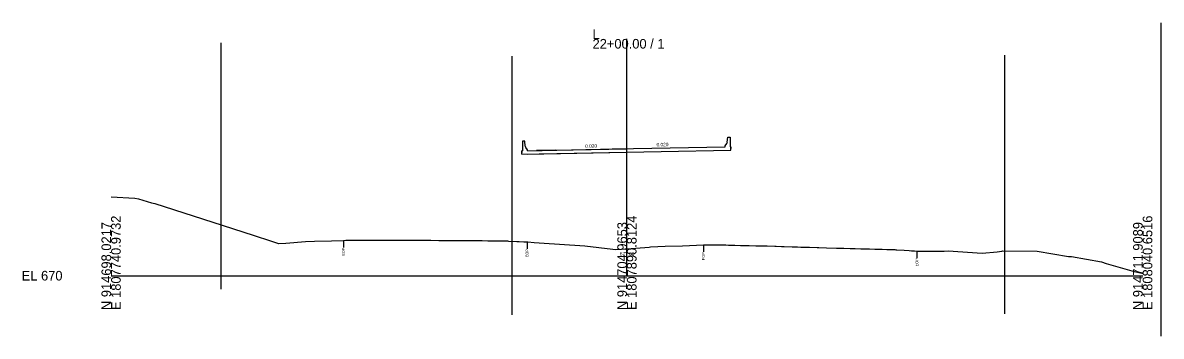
# Model space of a CAD drawing. Extents: x -26 to 1352, y -510 to 9596.
# Drawn here: x -25.7 to 305.4, y 7982.4 to 8073.6 of the extents above; entities that cross this region are included whole.
import ezdxf

# ---------------------------------------------------------------- set-up
doc = ezdxf.new("R2010")
doc.units = 0
for name, color, linetype in [('Default', 7, 'Continuous'), ('Exist Cross Section Cell', 7, 'Continuous'), ('Exist XS Center Line Elevation Label', 7, 'Continuous'), ('Exist XS Ground Line', 7, 'Continuous'), ('Old_Level_10', 7, 'Continuous'), ('Prop XS Bridge', 7, 'Continuous'), ('Prop XS Exc Vertical Line 1', 7, 'Continuous'), ('Prop XS Exc Vertical Line 2', 7, 'Continuous'), ('Prop XS Exc Vertical Line 3', 7, 'Continuous'), ('Prop XS Exc Vertical Line 4', 7, 'Continuous'), ('Prop XS SE Text', 7, 'Continuous')]:
    doc.layers.add(name, color=color, linetype=linetype)

msp = doc.modelspace()

# ---------------------------------------------------------------- linework, layer by layer
at = {"layer": 'Default'}
for p, q in [((119.63, 8039.14), (119.59, 8039.1)), ((119.59, 8039.1), (119.59, 8036.36)), ((120.26, 8039.14), (119.63, 8039.14)), ((120.29, 8039.1), (120.26, 8039.14)), ((120.44, 8037.71), (120.29, 8039.1)), ((179.2, 8038.86), (179.35, 8040.25)), ((179.35, 8040.25), (179.39, 8040.29)), ((179.39, 8040.29), (180.02, 8040.29)), ((180.02, 8040.29), (180.05, 8040.25)), ((180.05, 8040.25), (180.05, 8037.51)), ((119.46, 8035.32), (180.18, 8036.54)), ((119.53, 8036.36), (119.46, 8036.29)), ((119.46, 8035.32), (119.46, 8036.29)), ((119.46, 8036.29), (119.46, 8035.83)), ((119.59, 8036.36), (119.53, 8036.36)), ((121.07, 8036.62), (120.59, 8037.3)), ((121.07, 8036.36), (146.57, 8036.87)), ((121.07, 8036.36), (121.07, 8036.62)), ((121.09, 8035.36), (149.82, 8035.93)), ((150, 8036.93), (145.71, 8036.85)), ((146.57, 8036.87), (178.57, 8037.51)), ((178.57, 8037.77), (179.05, 8038.45)), ((178.57, 8037.51), (178.57, 8037.77)), ((180.05, 8037.51), (180.11, 8037.51)), ((180.11, 8037.51), (180.18, 8037.44)), ((180.18, 8037.44), (180.18, 8036.98)), ((180.18, 8036.54), (180.18, 8037.44))]:
    msp.add_line(p, q, dxfattribs=at)
for centre, start, end in [((178.34, 8038.95), 325.0087, 353.9889), ((121.3, 8037.8), 186.0111, 214.9913)]:
    msp.add_arc(centre, 0.869, start, end, dxfattribs=at)
at = {"layer": 'Exist Cross Section Cell'}
for p, q in [((150, 8000), (150, 8068.87)), ((0, 8000), (150, 8000)), ((150, 8000), (300, 8000))]:
    msp.add_line(p, q, dxfattribs=at)
at = {"layer": 'Exist XS Ground Line'}
msp.add_lwpolyline([(0, 8022.96), (6.93, 8022.55), (7.94, 8022.38), (11.73, 8021.21), (12.72, 8020.99), (32.33, 8014.67), (41.63, 8011.7), (46.33, 8010.11), (48.67, 8009.41), (48.81, 8009.37), (50.85, 8009.43), (56.48, 8009.92), (59.17, 8010.01), (64.11, 8010.17), (67.55, 8010.28), (68.27, 8010.29), (69.29, 8010.29), (70.41, 8010.31), (71.39, 8010.31), (72.94, 8010.32), (74.61, 8010.32), (75.42, 8010.32), (77.27, 8010.33), (77.91, 8010.33), (79.87, 8010.33), (80.7, 8010.35), (82.19, 8010.38), (82.68, 8010.37), (82.94, 8010.37), (85.11, 8010.35), (85.42, 8010.35), (85.69, 8010.35), (87.92, 8010.33), (90.39, 8010.32), (90.45, 8010.32), (91.65, 8010.31), (92.88, 8010.3), (92.93, 8010.3), (95.26, 8010.28), (95.44, 8010.28), (95.63, 8010.28), (97.94, 8010.27), (98.28, 8010.27), (98.52, 8010.27), (100.16, 8010.26), (100.53, 8010.26), (100.85, 8010.25), (102.97, 8010.24), (103.5, 8010.24), (105.46, 8010.22), (107.19, 8010.2), (107.94, 8010.2), (109.6, 8010.17), (110.45, 8010.16), (112.05, 8010.15), (112.97, 8010.13), (114.96, 8010.12), (115.13, 8010.12), (115.31, 8010.1), (115.59, 8010.09), (117.97, 8009.94), (118.64, 8009.92), (120.04, 8009.87), (120.95, 8009.85), (121.2, 8009.84), (123.03, 8009.68), (124.48, 8009.59), (137.73, 8008.69), (145.93, 8007.69), (146.6, 8007.61), (150, 8007.86), (156.46, 8008.34), (156.89, 8008.37), (161.13, 8008.54), (166.18, 8008.73), (172.26, 8008.96), (172.89, 8008.96), (173.62, 8008.95), (175.53, 8008.93), (176.54, 8008.95), (177.71, 8008.93), (178.31, 8008.95), (178.72, 8008.94), (179.56, 8008.92), (180.53, 8008.89), (181.36, 8008.87), (183.04, 8008.83), (184.83, 8008.79), (185.54, 8008.77), (187.48, 8008.73), (188.05, 8008.72), (190.12, 8008.66), (190.55, 8008.64), (190.82, 8008.64), (192.97, 8008.57), (193.37, 8008.56), (194.92, 8008.5), (195.27, 8008.5), (195.54, 8008.49), (195.72, 8008.48), (198.07, 8008.41), (198.16, 8008.41), (199.65, 8008.37), (200.58, 8008.34), (200.64, 8008.34), (203.09, 8008.27), (205.32, 8008.2), (205.55, 8008.2), (205.8, 8008.19), (208.05, 8008.11), (210.94, 8008.02), (210.95, 8008.02), (210.95, 8008.02), (212.95, 8007.98), (213.07, 8007.98), (214.89, 8007.93), (215.56, 8007.92), (216.33, 8007.9), (218.06, 8007.85), (219.64, 8007.8), (220.57, 8007.78), (222.08, 8007.74), (223.09, 8007.72), (224.24, 8007.68), (225.6, 8007.65), (226.01, 8007.64), (227.93, 8007.58), (228.17, 8007.56), (228.53, 8007.54), (230.6, 8007.38), (232.09, 8007.29), (232.8, 8007.25), (233.62, 8007.21), (234.32, 8007.17), (236.64, 8007.18), (239.04, 8007.18), (240.86, 8007.18), (242.28, 8007.17), (243.43, 8007.19), (253.3, 8006.54), (257.69, 8006.98), (259.01, 8007.09), (259.02, 8007.12), (259.33, 8007.24), (269.32, 8007.14), (278.42, 8005.6), (279.33, 8005.59), (287.98, 8004.01), (289.34, 8003.57), (297.55, 8001.2), (299.35, 8000.82), (300, 8000.64)], dxfattribs=at)
at = {"layer": 'Old_Level_10'}
for p, q in [((67.55, 8010.28), (67.55, 8008.23)), ((120.95, 8009.85), (120.95, 8007.8)), ((172.26, 8008.96), (172.26, 8006.91)), ((234.32, 8007.17), (234.32, 8005.12))]:
    msp.add_line(p, q, dxfattribs=at)
at = {"layer": 'Prop XS Bridge'}
for q in [(123.75, 8036.41), (150, 8036.93)]:
    msp.add_line((129.25, 8036.52), q, dxfattribs=at)
at = {"layer": 'Prop XS Exc Vertical Line 1'}
msp.add_line((31.98, 7996.06), (31.98, 8067.72), dxfattribs=at)
at = {"layer": 'Prop XS Exc Vertical Line 2'}
msp.add_line((116.64, 7988.63), (116.64, 8063.87), dxfattribs=at)
at = {"layer": 'Prop XS Exc Vertical Line 3'}
msp.add_line((259.9, 7988.9), (259.9, 8064.14), dxfattribs=at)
at = {"layer": 'Prop XS Exc Vertical Line 4'}
msp.add_line((305.38, 7982.38), (305.38, 8073.58), dxfattribs=at)

# ---------------------------------------------------------------- texts
at = {"layer": 'Exist Cross Section Cell'}
for s, p in [('L', (140, 8068.87)), ('22+00.00 / 1', (140, 8066.07)), ('EL 670', (-26, 7998.6))]:
    msp.add_text(s, height=2.8, dxfattribs=at).set_placement(p)
for s, p in [('N 914698.0217', (0, 7990)), ('E 1807740.9732', (2.8, 7990)), ('N 914704.9653', (150, 7990)), ('E 1807890.8124', (152.8, 7990)), ('N 914711.9089', (300, 7990)), ('E 1808040.6516', (302.8, 7990))]:
    msp.add_text(s, height=2.8, rotation=90, dxfattribs=at).set_placement(p)
at = {"layer": 'Exist XS Center Line Elevation Label'}
msp.add_text('677.86', height=1, dxfattribs=at).set_placement((147.95, 8005.86))
at = {"layer": 'Old_Level_10'}
for p in [(67.94, 8005.83), (121.34, 8005.4), (172.65, 8004.52), (234.71, 8002.72)]:
    msp.add_text('EOP', height=0.787, rotation=90, dxfattribs=at).set_placement(p)
at = {"layer": 'Prop XS SE Text'}
for p in [(158.63, 8037.61), (137.88, 8037.19)]:
    msp.add_text('0.020', height=1, rotation=1.1458, dxfattribs=at).set_placement(p)

doc.saveas('drawing.dxf')
